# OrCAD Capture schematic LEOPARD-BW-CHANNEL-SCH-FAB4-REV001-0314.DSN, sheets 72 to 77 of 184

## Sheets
72 111_AST1250 HARDWARE TRAPPING: size Custom; title: AST1250 HARDWARE STRAPPING
73 110_AST1250 POWER: size A3; title: AST1250 POWER
74 107_AST1250 PCIE_LPC_DDR3_I2C: size Custom; title: AST1250 PCIE_LPC_DDR3_I2C
75 106_10000uF CAPACITORS: size Custom; title: 10000uF CAPACITORS
76 105_AST1250 HEARTBEAT_ADC: size A3; title: AST1250 HEARTBEAT_ADC
77 104_SMBUS HEADER: size A3; title: SMBUS HEADER

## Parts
sheet 104_SMBUS HEADER
JP8  FCI-CON2-S-GP  [680001-202HLF]
JP9  FCI-CON2-S-GP  [680001-202HLF]
JP10  FCI-CON2-S-GP  [680001-202HLF]
JP12  FCI-CON2-S-GP  [680001-202HLF]
sheet 105_AST1250 HEARTBEAT_ADC
C7265  SC1U10V2KX-4-GP  [C402H22]
C7266  SCD1U16V2KX-3GP  [C402H22]
C7267  SCD1U16V2KX-3GP  [C402H22]
C7269  SCD1U16V2KX-3GP  [C402H22]
C7270  SCD1U16V2KX-3GP  [C402H22]
C7271  SCD1U16V2KX-3GP  [C402H22]
C7281  SCD1U16V2KX-3GP  [C402H22]
C7283  SCD1U16V2KX-3GP  [C402H22]
C7285  SC1U10V2KX-4-GP  [C402H22]
LED63  LED-G-62-GP-U  [LED1608AKH36]
LED64  LED-G-62-GP-U  [LED1608AKH36]
R2082  5K6R2F-2-GP  [R402H16]
R2083  1K8R2F-GP  [R402H16]
R2084  330R2J-3-GP  [R402H16]
R2085  1KR2F-3-GP  [R402H16]
R2086  1KR2F-3-GP  [R402H16]
R2087  1KR2F-3-GP  [R402H16]
R2088  1KR2F-3-GP  [R402H16]
R2089  1K2R2F-1-GP  [R402H16]
R2090  130R2F-1-GP  [R402H16]
R2092  1KR2F-3-GP  [R402H16]
R2093  1K2R2F-1-GP  [R402H16]
R2094  130R2F-1-GP  [R402H16]
R2097  1KR2F-3-GP  [R402H16]
R2104  1KR2F-3-GP  [R402H16]
R2105  1K8R2F-GP  [R402H16]
R2116  330R2J-3-GP  [R402H16]
R2124  0R2J-2-GP  [R402H16]
R2125  0R2J-2-GP  [R402H16]
R2128  0R2J-2-GP  [R402H16]
R2130  1KR2F-3-GP  [R402H16]
U150  SN74LVC06APW-GP-U  [TSOIC14H48]  (sections A,B,C,D,E,F)
sheet 106_10000uF CAPACITORS
TC3  SE680U16VM-4-GP  [SE421740H414]
TC4  SE680U16VM-4-GP  [SE421740H414]
TC5  SE680U16VM-4-GP  [SE421740H414]
TC10  SE680U16VM-4-GP  [SE421740H414]
TC11  SE680U16VM-4-GP  [SE421740H414]
TC12  SE680U16VM-4-GP  [SE421740H414]
TC15  SE680U16VM-4-GP  [SE421740H414]
sheet 107_AST1250 PCIE_LPC_DDR3_I2C
BMC1  AST1250A1-GP  [BGA408D19H52]  (sections A,B,C,D)
C115  SCD1U16V2KX-3GP  [C402H22]
C118  SCD1U16V2KX-3GP  [C402H22]
C121  SC1U16V3KX-5GP  [C603H36]
C124  SCD1U16V2KX-3GP  [C402H22]
C127  SC10U6D3V5KX-4GP  [C805H58]
C130  SCD1U16V2KX-3GP  [C402H22]
C133  SCD1U16V2KX-3GP  [C402H22]
C136  SCD1U16V2KX-3GP  [C402H22]
C139  SCD1U16V2KX-3GP  [C402H22]
C142  SCD1U16V2KX-3GP  [C402H22]
C145  SCD1U16V2KX-3GP  [C402H22]
C148  SCD1U16V2KX-3GP  [C402H22]
C149  SCD01U25V2KX-3GP  [C402H22]
C150  SCD1U16V2KX-3GP  [C402H22]
C151  SCD1U16V2KX-3GP  [C402H22]
C152  SCD01U25V2KX-3GP  [C402H22]
C707  SCD1U16V2KX-3GP  [C402H22]
C718  SCD1U16V2KX-3GP  [C402H22]
Q28  LMBT3904LT1G-GP  [SOT23CBE2D4H44]
R231  10KR2F-2-GP  [R402H16]
R402  0R2J-2-GP  [R402H16]
R411  191R2F-GP  [R402H16]
R422  0R2J-2-GP  [R402H16]
R656  0R2J-2-GP  [R402H16]
R657  100KR2F-L1-GP  [R402H16]
R712  4K7R2F-GP  [R402H16]
R714  4K7R2F-GP  [R402H16]
R810  4K7R2F-GP  [R402H16]
R815  1KR2F-3-GP  [R402H16]
R817  1KR2F-3-GP  [R402H16]
R822  240R2F-1-GP  [R402H16]
R823  1KR2F-3-GP  [R402H16]
R943  4K7R2F-GP  [R402H16]
R2034  1KR2J-1-GP  [R402H16]
R2035  1KR2J-1-GP  [R402H16]
R2036  1KR2F-3-GP  [R402H16]
R2037  1KR2F-3-GP  [R402H16]
R2038  1KR2F-3-GP  [R402H16]
R2039  1KR2F-3-GP  [R402H16]
R2040  1KR2F-3-GP  [R402H16]
R2041  2K2R2F-GP  [R402H16]
R2042  2K2R2F-GP  [R402H16]
R2046  1KR2F-3-GP  [R402H16]
R2047  4K7R2F-GP  [R402H16]
R2048  2K2R2F-GP  [R402H16]
R2049  2K2R2F-GP  [R402H16]
R2050  4K7R2F-GP  [R402H16]
R2051  4K7R2F-GP  [R402H16]
R2052  4K7R2F-GP  [R402H16]
R2055  2K2R2F-GP  [R402H16]
R2091  100KR2F-L1-GP  [R402H16]
R2095  2K2R2F-GP  [R402H16]
R2096  4K7R2F-GP  [R402H16]
U21  NTJD4001NT1G-1-GP  [SOT-363H44]
U33  NT5CB64M16FP-DH-GP  [BGA96D0913H48]
sheet 110_AST1250 POWER
C156  SCD1U16V2KX-3GP  [C402H22]
C157  SC1U10V2KX-4-GP  [C402H22]
C158  SCD1U16V2KX-3GP  [C402H22]
C159  SC1U10V2KX-4-GP  [C402H22]
C161  SCD1U16V2KX-3GP  [C402H22]
C163  SC1U10V2KX-4-GP  [C402H22]
C165  SC220P50V2KX-3GP  [C402H22]
C166  SCD1U16V2KX-3GP  [C402H22]
C167  SC1U10V2KX-4-GP  [C402H22]
C169  SC1U10V2KX-4-GP  [C402H22]
C170  SCD1U16V2KX-3GP  [C402H22]
C171  SC1U10V2KX-4-GP  [C402H22]
C172  SC1U10V2KX-4-GP  [C402H22]
C175  SC1U10V2KX-4-GP  [C402H22]
C178  SC4D7U16V5KX-1-GP  [C805H56]
C184  SCD1U16V2KX-3GP  [C402H22]
C190  SC220P50V2KX-3GP  [C402H22]
C193  SC1U10V2KX-4-GP  [C402H22]
C196  SC1U10V2KX-4-GP  [C402H22]
C197  SC100P50V2JN-3GP  [C402H22]
C198  SC1U10V2KX-4-GP  [C402H22]
C199  SC100P50V2JN-3GP  [C402H22]
C200  SC1U10V2KX-4-GP  [C402H22]
C201  SC1U10V2KX-4-GP  [C402H22]
C202  SC1U10V2KX-4-GP  [C402H22]
C203  SC1U10V2KX-4-GP  [C402H22]
C300  SC100P50V2JN-3GP  [C402H22]
C301  SC1U10V2KX-4-GP  [C402H22]
C302  SC1U10V2KX-4-GP  [C402H22]
C304  SC1U10V2KX-4-GP  [C402H22]
C305  SC1U10V2KX-4-GP  [C402H22]
C306  SC1U10V2KX-4-GP  [C402H22]
C308  SC1U10V2KX-4-GP  [C402H22]
C314  SC100P50V2JN-3GP  [C402H22]
L8  MMZ2012S601ATA1N-GP  [L805H42]
L9  MMZ2012S601ATA1N-GP  [L805H42]
L10  MMZ2012S601ATA1N-GP  [L805H42]
L11  MMZ2012S601ATA1N-GP  [L805H42]
R939  2K74R3F-GP  [R603H22]
R940  49K9R2F-L-GP  [R402H16]
sheet 111_AST1250 HARDWARE TRAPPING
JP1  FCI-CON3-S1-GP  [68001-203HLF]
R538  3K3R2F-2-GP  [R402H16]
R547  3K3R2F-2-GP  [R402H16]
R601  3K3R2F-2-GP  [R402H16]
R606  3K3R2F-2-GP  [R402H16]
R1060  3K3R2F-2-GP  [R402H16]
R1061  3K3R2F-2-GP  [R402H16]
R1062  3K3R2F-2-GP  [R402H16]
R1063  3K3R2F-2-GP  [R402H16]
R1064  3K3R2F-2-GP  [R402H16]
R1065  3K3R2F-2-GP  [R402H16]
R1066  3K3R2F-2-GP  [R402H16]
R1067  3K3R2F-2-GP  [R402H16]
R1068  3K3R2F-2-GP  [R402H16]
R1069  3K3R2F-2-GP  [R402H16]
R1070  3K3R2F-2-GP  [R402H16]
R1071  3K3R2F-2-GP  [R402H16]
R1072  3K3R2F-2-GP  [R402H16]
R1073  3K3R2F-2-GP  [R402H16]
R1074  3K3R2F-2-GP  [R402H16]
R1075  3K3R2F-2-GP  [R402H16]
R1076  3K3R2F-2-GP  [R402H16]
R1077  3K3R2F-2-GP  [R402H16]
R1078  3K3R2F-2-GP  [R402H16]
R1079  3K3R2F-2-GP  [R402H16]
R1080  3K3R2F-2-GP  [R402H16]
R1081  3K3R2F-2-GP  [R402H16]
R1082  3K3R2F-2-GP  [R402H16]
R1083  3K3R2F-2-GP  [R402H16]
R1084  3K3R2F-2-GP  [R402H16]
R1085  3K3R2F-2-GP  [R402H16]
R1086  3K3R2F-2-GP  [R402H16]
R1087  3K3R2F-2-GP  [R402H16]

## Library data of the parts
JP8-JP10 JP12 = FCI-CON2-S-GP: HEAD ML 1R2P 68001-202HLF; Category: PCH; GREENDFACTOR: R_SA;; Package Type: CONN-G4; Part Number: 21.65007.102; Part Type: CONN-G4; SPEC: http://wpqssvr.wistron.com.tw:7001/wpqs/servlet/COM.qpart.Attachment?PartNumber=21.65007.102
C157 C159 C163 C167 C169 C171 C172 C175 C193 C196 C198 C200-C203 C301 C302 C304-C306 C308 C7265 C7285 = SC1U10V2KX-4-GP: CHIP CAP C 1U 10V K 0402 X6S; GREENDFACTOR: R2_SA;HF_SA;; Part Number: 78.10523.8FL; Part Type: SMD-BCG6; SPEC: http://wpqssvr.wistron.com.tw:7001/wpqs/servlet/COM.qpart.Attachment?PartNumber=78.10523.8FL
C7266 C7267 C7269-C7271 C7281 C7283 = SCD1U16V2KX-3GP: CHIP CAP C 0.1U 16V K0402 X7R; CATEGORIES: CAP_1.xV; GREENDFACTOR: R2_SA;HF_SA;G_SA;; MAIN_SOURCE: M; Part Number: 78.10421.2FL; Part Type: SMD-BCG; SPEC: http://wpqssvr.wistron.com.tw:7001/wpqs/servlet/COM.qpart.Attachment?PartNumber=78.10421.2FL
LED63 LED64 = LED-G-62-GP-U: LED GREEN LTST-C190GKT SMD; Alternate: 83.19213.I70; Category: BMC; DESCRIPTIO: LED GREEN LTST-C190GKT SMD; GREENDFACTOR: R2_SA;; Package Type: DISCRET-G9; Part Number: 83.00190.Q70; Part Type: DISCRET-G9; SPEC: http://wpqssvr.wistron.com.tw:7001/wpqs/servlet/COM.qpart.Attachment?PartNumber=83.00190.Q70; VENDORPARTNUMBER: LTST-C190GKT
R2082 = 5K6R2F-2-GP: CHIP RES 5.6K F 1/16W 0402(ROH; Category: HW monitor; DESCRIPTIO: CHIP RES 5.6K F 1/16W 0402(ROH; GREENDFACTOR: R2_SA;HF_SA;G_SA;; Package Type: SMD-RG; Part Number: 64.56015.6DL; Part Type: SMD-RG; SPEC: http://wpqssvr.wistron.com.tw:7001/wpqs/servlet/COM.qpart.Attachment?PartNumber=64.56015.6DL; VENDORPARTNUMBER: RM04FTN5601/RTT025601FTH/RR0510S-562-FN/RC0402FR-075K6L
R2083 R2105 = 1K8R2F-GP: CHIP RES 1.8K F 1/16W 0402; Category: HW monitor; DESCRIPTIO: CHIP RES 1.8K F 1/16W 0402; GREENDFACTOR: R2_SA;HF_SA;G_SA;; Package Type: SMD-RG; Part Number: 64.18015.6DL; Part Type: SMD-RG; SPEC: http://wpqssvr.wistron.com.tw:7001/wpqs/servlet/COM.qpart.Attachment?PartNumber=64.18015.6DL; VENDORPARTNUMBER: RM04FTN1801/RTT021801FTH/RR0510S-182-FN /RC0402FR-071K8L
R2084 R2116 = 330R2J-3-GP: CHIP RES 330 J 1/16W 0402; Category: BMC; DESCRIPTIO: CHIP RES 330 J 1/16W 0402; GREENDFACTOR: R2_SA;HF_SA;G_SA;; Package Type: SMD-RG; Part Number: 63.33134.1DL; Part Type: SMD-RG; SPEC: http://wpqssvr.wistron.com.tw:7001/wpqs/servlet/COM.qpart.Attachment?PartNumber=63.33134.1DL; VENDORPARTNUMBER: RM04JTN331 / RTT02331JTH / RR0510S-331-JN / RC0402JR-07330RL/WR04X331JTL
R2085-R2088 R2092 R2097 R2104 = 1KR2F-3-GP: CHIP RES 1K F 1/16W 0402; Category: HW monitor; DESCRIPTIO: CHIP RES 1K F 1/16W 0402; GREENDFACTOR: R2_SA;HF_SA;G_SA;; Package Type: SMD-RG; Part Number: 64.10015.6DL; Part Type: SMD-RG; SPEC: http://wpqssvr.wistron.com.tw:7001/wpqs/servlet/COM.qpart.Attachment?PartNumber=64.10015.6DL; VENDORPARTNUMBER: RM04FTN1001 / RTT021001FTH / RR0510S-1001-FN / RC0402FR-071KL/WR04X1001FTL
R2089 R2093 = 1K2R2F-1-GP: CHIP RES 1.2K F 1/16W 0402; Category: BMC; DESCRIPTIO: CHIP RES 1.2K F 1/16W 0402; GREENDFACTOR: R2_SA;HF_SA;G_SA;; Package Type: SMD-RG; Part Number: 64.12015.6DL; Part Type: SMD-RG; SPEC: http://wpqssvr.wistron.com.tw:7001/wpqs/servlet/COM.qpart.Attachment?PartNumber=64.12015.6DL; VENDORPARTNUMBER: RM04FTN1201/RTT021201FTH/RR0510S-1201-FN/RC0402FR-071K2L/WR04X1201FTL
R2090 R2094 = 130R2F-1-GP: CHIP RES 130 F 1/16W 0402; GREENDFACTOR: R2_SA;HF_SA;G_SA;; Part Number: 64.13005.6DL; Part Type: SMD-RG; SPEC: http://wpqssvr.wistron.com.tw:7001/wpqs/servlet/COM.qpart.Attachment?PartNumber=64.13005.6DL
R2124 R2128 = 0R2J-2-GP: CHIP RES 0 J 1/16W 0402; Category: LOM - i350; DESCRIPTIO: CHIP RES 0 J 1/16W 0402; GREENDFACTOR: R2_SA;HF_SA;G_SA;; Package Type: SMD-RG; Part Number: 63.R0034.1DL; Part Type: SMD-RG; SPEC: http://wpqssvr.wistron.com.tw:7001/wpqs/servlet/COM.qpart.Attachment?PartNumber=63.R0034.1DL; VENDORPARTNUMBER: RM04JTN0/RTT02000JTH/RR0510X-000-XN/RC0402JR-070RL/WR04X000 PTL
R2125 = 0R2J-2-GP: CHIP RES 0 J 1/16W 0402; Category: LOM - i350; DESCRIPTIO: CHIP RES 0 J 1/16W 0402; GREENDFACTOR: R2_SA;HF_SA;G_SA;; POP?: NOPOP; Package Type: SMD-RG; Part Number: 63.R0034.1DL; Part Type: SMD-RG; SPEC: http://wpqssvr.wistron.com.tw:7001/wpqs/servlet/COM.qpart.Attachment?PartNumber=63.R0034.1DL; VENDORPARTNUMBER: RM04JTN0/RTT02000JTH/RR0510X-000-XN/RC0402JR-070RL/WR04X000 PTL
R2130 = 1KR2F-3-GP: CHIP RES 1K F 1/16W 0402; Category: HW monitor; DESCRIPTIO: CHIP RES 1K F 1/16W 0402; GREENDFACTOR: R2_SA;HF_SA;G_SA;; POP?: NOPOP; Package Type: SMD-RG; Part Number: 64.10015.6DL; Part Type: SMD-RG; SPEC: http://wpqssvr.wistron.com.tw:7001/wpqs/servlet/COM.qpart.Attachment?PartNumber=64.10015.6DL; VENDORPARTNUMBER: RM04FTN1001 / RTT021001FTH / RR0510S-1001-FN / RC0402FR-071KL/WR04X1001FTL
U150 = SN74LVC06APW-GP-U: IC CMOS SN74LVC06APWR TSSOP14P; GREENDFACTOR: R2_SA;; Part Number: 73.07406.BHB; Part Type: TTL-G3; SPEC: http://wpqssvr.wistron.com.tw:7001/wpqs/servlet/COM.qpart.Attachment?PartNumber=73.07406.BHB
TC3-TC5 TC10-TC12 TC15 = SE680U16VM-4-GP: CHIP CAP EL 680U 16V M 10*10.5 TZV; GREENDFACTOR: R2_C;; Part Number: 079.6871D.0011; Part Type: SMD-TCG2; SPEC: http://wpqssvr.wistron.com.tw:7001/wpqs/servlet/COM.qpart.Attachment?PartNumber=079.6871D.0011
BMC1 = AST1250A1-GP: IC BMC AST1250A1-GP TFBGA 408P; GREENDFACTOR: R2_C;; Part Number: 71.01250.A0U; Part Type: ASIC2-G7; SPEC: http://wpqssvr.wistron.com.tw:7001/wpqs/servlet/COM.qpart.Attachment?PartNumber=71.01250.A0U
C115 C118 C124 C130 C136 C139 C142 C145 C148 C150 C151 = SCD1U16V2KX-3GP: CHIP CAP C 0.1U 16V K0402 X7R; CATEGORIES: CAP_1.xV; Category: BMC; DESCRIPTIO: CHIP CAP C 0.1U 16V K0402 X7R; GREENDFACTOR: R2_SA;HF_SA;G_SA;; Level: SMD; MAIN_SOURCE: M; Package Type: SMD-BCG; Part Number: 78.10421.2FL; Part Type: SMD-BCG; SPEC: http://wpqssvr.wistron.com.tw:7001/wpqs/servlet/COM.qpart.Attachment?PartNumber=78.10421.2FL; Status: POP
C121 = SC1U16V3KX-5GP: CHIP CAP C 1U 16V K0603 X7R; CATEGORIES: CAP_Small; Category: BMC; GREENDFACTOR: R2_SA;HF_SA;G_SA;; Level: SMD; MAIN_SOURCE: M; Part Number: 78.10521.2BL; Part Type: SMD-BCG3; SPEC: http://wpqssvr.wistron.com.tw:7001/wpqs/servlet/COM.qpart.Attachment?PartNumber=78.10521.2BL; Status: POP
C127 = SC10U6D3V5KX-4GP: CHIP CAP C 10U 6.3V K0805 X7R; GREENDFACTOR: R2_SA;HF_SA;G_SA;; Part Number: 78.10620.21L; Part Type: SMD-BCG; SPEC: http://wpqssvr.wistron.com.tw:7001/wpqs/servlet/COM.qpart.Attachment?PartNumber=78.10620.21L
C133 C158 C184 = SCD1U16V2KX-3GP: CHIP CAP C 0.1U 16V K0402 X7R; CATEGORIES: CAP_1.xV; Category: BMC; GREENDFACTOR: R2_SA;HF_SA;G_SA;; Level: SMD; MAIN_SOURCE: M; Part Number: 78.10421.2FL; Part Type: SMD-BCG; SPEC: http://wpqssvr.wistron.com.tw:7001/wpqs/servlet/COM.qpart.Attachment?PartNumber=78.10421.2FL; Status: POP
C149 C152 = SCD01U25V2KX-3GP: CHIP 0.01U 25V K0402 X7R(ROHS); Category: BMC; GREENDFACTOR: R2_SA;HF_SA;G_SA;; Level: SMD; Part Number: 78.10322.2FL; Part Type: SMD-BCG; SPEC: http://wpqssvr.wistron.com.tw:7001/wpqs/servlet/COM.qpart.Attachment?PartNumber=78.10322.2FL; Status: POP
C707 C718 = SCD1U16V2KX-3GP: CHIP CAP C 0.1U 16V K0402 X7R; Category: PCH; GREENDFACTOR: R_SA;HF_SA;G_SA;; POP?: NOPOP; Part Number: 78.10421.2FL; Quotation: 13_8; Type: SMD
Q28 = LMBT3904LT1G-GP: XTOR LMBT3904LT1G NPN SOT-23; GREENDFACTOR: R2_SA;HF_SA;G_SA;; POP?: NOPOP; Part Number: 84.T3904.H11; Part Type: DISCRET-G6; SPEC: http://wpqssvr.wistron.com.tw:7001/wpqs/servlet/COM.qpart.Attachment?PartNumber=84.T3904.H11
R231 = 10KR2F-2-GP: CHIP RES 10K F 1/16W 0402; GREENDFACTOR: R2_SA;HF_SA;G_SA;; Part Number: 64.10025.6DL; Part Type: SMD-RG; SPEC: http://wpqssvr.wistron.com.tw:7001/wpqs/servlet/COM.qpart.Attachment?PartNumber=64.10025.6DL
R402 = 0R2J-2-GP: CHIP RES 0 J 1/16W 0402; Category: PCH; DESCRIPTIO: CHIP RES 0 J 1/16W 0402; GREENDFACTOR: R2_SA;HF_SA;G_SA;; POP?: NOPOP; Package Type: SMD-RG; Part Number: 63.R0034.1DL; Part Type: SMD-RG; SPEC: http://wpqssvr.wistron.com.tw:7001/wpqs/servlet/COM.qpart.Attachment?PartNumber=63.R0034.1DL; VENDORPARTNUMBER: RM04JTN0/RTT02000JTH/RR0510X-000-XN/RC0402JR-070RL/WR04X000 PTL
R411 = 191R2F-GP: CHIP RES 191 F 1/16W 0402; GREENDFACTOR: R2_SA;HF_SA;G_SA;; Part Number: 64.19105.6DL; Part Type: SMD-RG1; SPEC: http://wpqssvr.wistron.com.tw:7001/wpqs/servlet/COM.qpart.Attachment?PartNumber=64.19105.6DL
R422 = 0R2J-2-GP: CHIP RES 0 J 1/16W 0402; Category: PCH; DESCRIPTIO: CHIP RES 0 J 1/16W 0402; GREENDFACTOR: R2_SA;HF_SA;G_SA;; Package Type: SMD-RG; Part Number: 63.R0034.1DL; Part Type: SMD-RG; SPEC: http://wpqssvr.wistron.com.tw:7001/wpqs/servlet/COM.qpart.Attachment?PartNumber=63.R0034.1DL; VENDORPARTNUMBER: RM04JTN0/RTT02000JTH/RR0510X-000-XN/RC0402JR-070RL/WR04X000 PTL
R656 = 0R2J-2-GP: CHIP RES 0 J 1/16W 0402; GREENDFACTOR: R2_SA;HF_SA;G_SA;; POP?: NOPOP; Package Type: SMD-RG; Part Number: 63.R0034.1DL; SPEC: http://wpqssvr.wistron.com.tw:7001/wpqs/servlet/COM.qpart.Attachment?PartNumber=63.R0034.1DL
R657 = 100KR2F-L1-GP: CHIP RES 100K F 1/16W 0402; Category: BMC; GREENDFACTOR: R2_SA;R_SA;HF_SA;G_SA;; Level: SMD; Part Number: 64.10035.6DL; Part Type: SMD-RG; SPEC: http://wpqssvr.wistron.com.tw:7001/wpqs/servlet/COM.qpart.Attachment?PartNumber=64.10035.6DL; Status: POP
R712 = 4K7R2F-GP: CHIP RES 4.7K F 1/16W 0402; GREENDFACTOR: R2_SA;HF_SA;G_SA;; Package Type: RCL_GP; Part Number: 64.47015.6DL; SPEC: http://wpqssvr.wistron.com.tw:7001/wpqs/servlet/COM.qpart.Attachment?PartNumber=64.47015.6DL
R714 = 4K7R2F-GP: CHIP RES 4.7K F 1/16W 0402; GREENDFACTOR: R2_SA;HF_SA;G_SA;; POP?: NOPOP; Package Type: RCL_GP; Part Number: 64.47015.6DL; SPEC: http://wpqssvr.wistron.com.tw:7001/wpqs/servlet/COM.qpart.Attachment?PartNumber=64.47015.6DL
R810 = 4K7R2F-GP: CHIP RES 4.7K F 1/16W 0402; Category: BMC; DESCRIPTIO: CHIP RES 4.7K F 1/16W 0402; GREENDFACTOR: R2_SA;HF_SA;G_SA;; Level: SMD; Package Type: RCL_GP; Part Number: 64.47015.6DL; Part Type: RCL_GP; SPEC: http://wpqssvr.wistron.com.tw:7001/wpqs/servlet/COM.qpart.Attachment?PartNumber=64.47015.6DL; Status: POP
R815 R823 = 1KR2F-3-GP: CHIP RES 1K F 1/16W 0402; Category: BMC; GREENDFACTOR: R2_SA;R_SA;HF_SA;G_SA;; Level: SMD; Part Number: 64.10015.6DL; Part Type: SMD-RG; SPEC: http://wpqssvr.wistron.com.tw:7001/wpqs/servlet/COM.qpart.Attachment?PartNumber=64.10015.6DL; Status: POP
R817 = 1KR2F-3-GP: CHIP RES 1K F 1/16W 0402; Category: BMC; DESCRIPTIO: CHIP RES 1K F 1/16W 0402; GREENDFACTOR: R2_SA;R_SA;HF_SA;G_SA;; Level: SMD; Package Type: SMD-RG; Part Number: 64.10015.6DL; Part Type: SMD-RG; SPEC: http://wpqssvr.wistron.com.tw:7001/wpqs/servlet/COM.qpart.Attachment?PartNumber=64.10015.6DL; Status: POP
R822 = 240R2F-1-GP: CHIP RES 240 F 1/16W 0402(ROHS; Category: BMC; DESCRIPTIO: CHIP RES 240 F 1/16W 0402(ROHS; GREENDFACTOR: R2_SA;HF_SA;G_SA;; Level: SMD; Package Type: SMD-RG; Part Number: 64.24005.6DL; Part Type: SMD-RG; SPEC: http://wpqssvr.wistron.com.tw:7001/wpqs/servlet/COM.qpart.Attachment?PartNumber=64.24005.6DL; Status: POP
R943 = 4K7R2F-GP: CHIP RES 4.7K F 1/16W 0402; Category: CPU SIDE BAND; POP?: NOPOP; Part Number: 64.47015.6DL; Part Type: RCL_GP
R2034 R2035 = 1KR2J-1-GP: CHIP RES 1K J 1/16W 0402; GREENDFACTOR: R2_SA;HF_SA;G_SA;; Part Number: 63.10234.1DL; Part Type: SMD-RG; SPEC: http://wpqssvr.wistron.com.tw:7001/wpqs/servlet/COM.qpart.Attachment?PartNumber=63.10234.1DL
R2036-R2040 R2046 = 1KR2F-3-GP: CHIP RES 1K F 1/16W 0402; GREENDFACTOR: R2_SA;HF_SA;G_SA;; Package Type: SMD-RG; Part Number: 64.10015.6DL; SPEC: http://wpqssvr.wistron.com.tw:7001/wpqs/servlet/COM.qpart.Attachment?PartNumber=64.10015.6DL
R2041 R2042 R2048 R2049 R2055 R2095 = 2K2R2J-2-GP: CHIP RES 2.2K F 1/16W 0402; Category: BMC; DESCRIPTIO: CHIP RES 2.2K J 1/16W 0402; GREENDFACTOR: R2_SA;HF_SA;G_SA;; Package Type: RCL_GP; Part Number: 64.22015.6DL; Part Type: RCL_GP; SPEC: http://wpqssvr.wistron.com.tw:7001/wpqs/servlet/COM.qpart.Attachment?PartNumber=64.22015.6DL; VENDORPARTNUMBER: RM04FTN2201/RTT022201FTH/RR0510S-222-FN/RC0402FR-072K2L
R2047 R2050 R2096 = 4K7R2F-GP: CHIP RES 4.7K F 1/16W 0402; Category: BMC; DESCRIPTIO: CHIP RES 4.7K F 1/16W 0402; GREENDFACTOR: R2_SA;HF_SA;G_SA;; Package Type: RCL_GP; Part Number: 64.47015.6DL; Part Type: RCL_GP; SPEC: http://wpqssvr.wistron.com.tw:7001/wpqs/servlet/COM.qpart.Attachment?PartNumber=64.47015.6DL; VENDORPARTNUMBER: RM04FTN4701/RTT024701FTH/RR0510S-472-FN/RC0402FR-074K7L/WR04X4701FTL
R2051 R2052 = 4K7R2F-GP: CHIP RES 4.7K F 1/16W 0402; Category: BMC; DESCRIPTIO: CHIP RES 4.7K F 1/16W 0402; GREENDFACTOR: R2_SA;HF_SA;G_SA;; POP?: NOPOP; Package Type: RCL_GP; Part Number: 64.47015.6DL; Part Type: RCL_GP; SPEC: http://wpqssvr.wistron.com.tw:7001/wpqs/servlet/COM.qpart.Attachment?PartNumber=64.47015.6DL; VENDORPARTNUMBER: RM04FTN4701/RTT024701FTH/RR0510S-472-FN/RC0402FR-074K7L/WR04X4701FTL
R2091 = 100KR2F-L1-GP: CHIP RES 100K F 1/16W 0402; Category: BMC; DESCRIPTIO: CHIP RES 100K F 1/16W 0402; GREENDFACTOR: R2_SA;HF_SA;G_SA;; Package Type: SMD-RG; Part Number: 64.10035.6DL; Part Type: SMD-RG; SPEC: http://wpqssvr.wistron.com.tw:7001/wpqs/servlet/COM.qpart.Attachment?PartNumber=64.10035.6DL; VENDORPARTNUMBER: RM04FTN1003 / RTT021003FTH / RR0510S-1003-FN / RC0402FR-07100KL/WR04X1003FTL
U21 = NTJD4001NT1G-1-GP: IC MOSFET NTJD4001NT1G NC SOT-363 6P; GREENDFACTOR: R2_SA;; Part Number: 75.04001.07C; Part Type: DISCRET-G5; SPEC: http://wpqssvr.wistron.com.tw:7001/wpqs/servlet/COM.qpart.Attachment?PartNumber=75.04001.07C
U33 = NT5CB64M16FP-DH-GP: IC SDRAM NT5CB64M16FP-DH FBGA 96BALLS; GREENDFACTOR: R2_SA;HF_SA;G_SA;; POP?: 72.41164.V0U; Part Number: 72.56416.P0U; Part Type: MEMORY-G4; SPEC: http://wpqssvr.wistron.com.tw:7001/wpqs/servlet/COM.qpart.Attachment?PartNumber=72.56416.P0U
C156 C166 C170 = SCD1U16V2KX-3GP: CHIP CAP C 0.1U 16V K0402 X7R; CATEGORIES: CAP_1.xV; Category: BMC; GREENDFACTOR: R2_SA;HF_SA;G_SA;; Level: SMD; MAIN_SOURCE: M; POP?: NOPOP; Part Number: 78.10421.2FL; Part Type: SMD-BCG; SPEC: http://wpqssvr.wistron.com.tw:7001/wpqs/servlet/COM.qpart.Attachment?PartNumber=78.10421.2FL; Status: POP
C161 = SCD47U6D3V2KX-GP: CHIP CAP C 0.1U 16V K0402 X7R; CATEGORIES: CAP_1.xV; Category: BMC; GREENDFACTOR: R2_SA;HF_SA;G_SA;; Level: SMD; MAIN_SOURCE: M; Part Number: 78.10421.2FL; Part Type: SMD-BCG; SPEC: http://wpqssvr.wistron.com.tw:7001/wpqs/servlet/COM.qpart.Attachment?PartNumber=78.10421.2FL; Status: POP
C165 C190 = SC220P50V2KX-3GP: CHIP CAP 220P50V K0402 X7R(ROH; CATEGORIES: CAP_Small; Category: BMC; GREENDFACTOR: R2_SA;HF_SA;G_SA;; Level: SMD; MAIN_SOURCE: M; Part Number: 78.22124.2FL; Part Type: SMD-BCG; SPEC: http://wpqssvr.wistron.com.tw:7001/wpqs/servlet/COM.qpart.Attachment?PartNumber=78.22124.2FL; Status: POP
C178 = SC4D7U16V5KX-1-GP: CHIP CAP C 4.7U 16V K0805 X7R; GREENDFACTOR: R2_SA;HF_SA;G_SA;; Part Number: 78.47521.21L; Part Type: SMD-BCG2; SPEC: http://wpqssvr.wistron.com.tw:7001/wpqs/servlet/COM.qpart.Attachment?PartNumber=78.47521.21L
C197 C199 = SC100P50V2JN-3GP: CHIP CAP 100P50V J0402 NPO(ROH; CATEGORIES: CAP_Small; Category: BMC; GREENDFACTOR: R2_SA;HF_SA;G_SA;; Level: SMD; MAIN_SOURCE: M; Part Number: 78.10134.1FL; Part Type: SMD-BCG; SPEC: http://wpqssvr.wistron.com.tw:7001/wpqs/servlet/COM.qpart.Attachment?PartNumber=78.10134.1FL; Status: POP
C300 C314 = SC220P50V2KX-3GP: CHIP CAP 100P50V J0402 NPO(ROH; CATEGORIES: CAP_Small; Category: BMC; GREENDFACTOR: R2_SA;HF_SA;G_SA;; Level: SMD; MAIN_SOURCE: M; Part Number: 78.10134.1FL; Part Type: SMD-BCG; SPEC: http://wpqssvr.wistron.com.tw:7001/wpqs/servlet/COM.qpart.Attachment?PartNumber=78.10134.1FL; Status: POP
L8-L11 = MMZ2012S601ATA1N-GP: CHIP BEAD MMZ2012S601ATA1N TDK; Category: BMC; GREENDFACTOR: R_C;; Level: SMD; Part Number: 68.00109.171; Part Type: DISCRET-G5; SPEC: http://wpqssvr.wistron.com.tw:7001/wpqs/servlet/COM.qpart.Attachment?PartNumber=68.00109.171; Status: POP
R939 = 2K74R3F-GP: CHIP RES 2.74K F 1/10W 0603; Category: BMC; Level: SMD; Part Number: 64.27415.55L; Part Type: RCL_GP; Status: POP
R940 = 49K9R2F-L-GP: CHIP RES 49.9K F 1/16W 0402; Category: BMC; GREENDFACTOR: R2_SA;R_SA;HF_SA;G_SA;; Level: SMD; POP?: POP; Part Number: 64.49925.6DL; Part Type: SMD-RG; SPEC: http://wpqssvr.wistron.com.tw:7001/wpqs/servlet/COM.qpart.Attachment?PartNumber=64.49925.6DL; Status: POP
JP1 = FCI-CON3-S1-GP: HEAD ML 1R3P ST 68001-203HLF; Category: PCH; GREENDFACTOR: R_SA;; Green Factor: R_SA;; Part Number: 21.61084.103; Part Type: CONN-G4; ROOM: IMMv2; S/D: DIP; SPEC: http://wpqssvr.wistron.com.tw:7001/wpqs/servlet/COM.qpart.Attachment?PartNumber=21.61084.103; Vender: FCI
R538 R1060 R1062 R1064 R1070 R1082 R1083 = 3K3R2F-2-GP: CHIP RES 3.3K F 1/16W 0402; Category: BMC; GREENDFACTOR: R2_SA;HF_SA;G_SA;; Level: SMD; Part Number: 64.33015.6DL; Part Type: SMD-RG; SPEC: http://wpqssvr.wistron.com.tw:7001/wpqs/servlet/COM.qpart.Attachment?PartNumber=64.33015.6DL
R547 R601 R606 R1061 R1063 R1065-R1069 R1071-R1081 R1084-R1086 = 3K3R2F-2-GP: CHIP RES 3.3K F 1/16W 0402; Category: BMC; GREENDFACTOR: R2_SA;HF_SA;G_SA;; Level: SMD; POP?: NOPOP; Part Number: 64.33015.6DL; Part Type: SMD-RG; SPEC: http://wpqssvr.wistron.com.tw:7001/wpqs/servlet/COM.qpart.Attachment?PartNumber=64.33015.6DL
R1087 = 3K3R2F-2-GP: CHIP RES 3.3K F 1/16W 0402; Category: BMC; GREENDFACTOR: R2_SA;HF_SA;G_SA;; Level: SMD; Part Number: 64.33015.6DL; Part Type: SMD-RG; SPEC: http://wpqssvr.wistron.com.tw:7001/wpqs/servlet/COM.qpart.Attachment?PartNumber=64.33015.6DL; Status: POP

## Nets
GND: BMC1.AA18(PLLVSS) BMC1.AA19(PLLVSS) BMC1.D21(PEAGND) BMC1.D22(PEAGND) BMC1.J9(GND) BMC1.J10(GND) BMC1.J11(GND) BMC1.J12(GND) BMC1.J13(GND) BMC1.J14(GND) BMC1.K9(GND) BMC1.K10(GND) BMC1.K11(GND) BMC1.K12(GND) BMC1.K13(GND) BMC1.K14(GND) BMC1.L9(GND) BMC1.L10(GND) BMC1.L11(GND) BMC1.L12(GND) BMC1.L13(GND) BMC1.L14(GND) BMC1.M9(GND) BMC1.M10(GND) BMC1.M11(GND) BMC1.M12(GND) BMC1.M13(GND) BMC1.M14(GND) BMC1.N9(GND) BMC1.N10(GND) BMC1.N11(GND) BMC1.N12(GND) BMC1.N13(GND) BMC1.N14(GND) BMC1.P4(ADCAVSS) BMC1.P9(GND) BMC1.P10(GND) BMC1.P11(GND) BMC1.P12(GND) BMC1.P13(GND) BMC1.P14(GND) BMC1.R5(DACAVSS) BMC1.V18(PLLVSS) C115.2 C118.2 C121.2 C124.2 C127.2 C130.2 C133.1 C136.2 C139.2 C142.2 C145.2 C148.2 C149.2 C150.2 C151.2 C157.2 C158.2 C159.2 C161.2 C163.2 C165.2 C166.1 C167.2 C169.2 C171.2 C172.2 C175.2 C178.2 C184.2 C190.2 C193.2 C196.2 C197.2 C198.2 C199.2 C200.2 C201.2 C202.2 C203.2 C300.2 C301.2 C302.2 C304.2 C305.2 C306.2 C308.2 C314.2 C7265.2 C7266.2 C7267.2 C7269.2 C7270.2 C7271.2 C7281.2 C7283.2 C7285.2 R411.2 R657.1 R815.2 R822.1 R939.1 R940.1 R2085.2 R2086.2 R2087.2 R2091.2 R2092.2 R2104.2 R2125.2 R2130.2 TC3.2 TC4.2 TC5.2 TC10.2 TC11.2 TC12.2 TC15.2 U21.1(S1) U21.4(S2) U33.A9(VSS) U33.B1(VSSQ) U33.B3(VSS) U33.B9(VSSQ) U33.D1(VSSQ) U33.D8(VSSQ) U33.E1(VSS) U33.E2(VSSQ) U33.E8(VSSQ) U33.F9(VSSQ) U33.G1(VSSQ) U33.G8(VSS) U33.G9(VSSQ) U33.J2(VSS) U33.J8(VSS) U33.M1(VSS) U33.M9(VSS) U33.P1(VSS) U33.P9(VSS) U33.T1(VSS) U33.T9(VSS) U150.5(I) U150.7(GND) U150.9(I) U150.13(I) ; also on sheet 1 2 3 4 5 6 7 8 9 10 11 12 13 14 15 16 17 18 19 20 21 22 23 24 25 26 27 28 29 30 31 32 33 34 35 36 37 38 39 44 46 47 49 50 51 52 53 54 55 56 57 58 59 60 61 62 63 64 65 66 69 70 71 78 79 80 81 82 83 84 86 87 88 89 90 91 92 93 94 95 96 97 98 99 100 101 102 103 104 105 106 107 108 109 110 111 112 113 114 115 116 117 118 119 128 129 138 139 159 160 161 166 168 169 170 171 172 173 174 175 176 177 180 181 182 183 184
P1V05_STBY_PCH: R2124.1 ; also on sheet 9 45 87
P1V8_STBY: R2128.1 ; also on sheet 5 6 7 8
P1V26_STBY: BMC1.F14(IV12D) BMC1.F15(IV12D) BMC1.K6(IV12D) BMC1.K17(PEAV12) BMC1.L6(IV12D) BMC1.L17(IV12D) BMC1.P6(IV12D) BMC1.P17(IV12D) BMC1.R6(IV12D) BMC1.R17(IV12D) BMC1.U12(IV12D) BMC1.U13(IV12D) BMC1.Y18(MPLLDV12) C157.1 C169.1 C172.1 C201.1 C203.1 C302.1 L9.1(F) ; also on sheet 5
P1V538_STBY: BMC1.U10(MVDD) BMC1.U11(MVDD) BMC1.U14(MVDD) BMC1.U15(MVDD) C115.1 C118.1 C124.1 C127.1 C130.1 C136.1 C142.1 C145.1 C148.1 C150.1 C151.1 C152.1 C163.1 C167.1 C193.1 C196.1 R817.2 R823.1 U33.A1(VDDQ) U33.A8(VDDQ) U33.B2(VDD) U33.C1(VDDQ) U33.C9(VDDQ) U33.D2(VDDQ) U33.D9(VDD) U33.E9(VDDQ) U33.F1(VDDQ) U33.G7(VDD) U33.H2(VDDQ) U33.H9(VDDQ) U33.K2(VDD) U33.K8(VDD) U33.N1(VDD) U33.N9(VDD) U33.R1(VDD) U33.R9(VDD) ; also on sheet 6
P3V3: R712.2 R943.1 R2088.1 ; also on sheet 1 3 8 45 46 48 49 52 54 58 65 78 83 84 87 90 91 94 95 96 100 101 102 161 166 168 173 174 177 180 181 182 183
P3V3_STBY: BMC1.F8(R2VDD) BMC1.F9(R2VDD) BMC1.F10(R1VDD) BMC1.F11(R1VDD) BMC1.F12(PV33D) BMC1.F13(PV33D) BMC1.H6(PV33D) BMC1.H17(PV33D) BMC1.J6(PV33D) BMC1.J17(PEAV33) BMC1.M6(PV33D) BMC1.M17(PV33D) BMC1.N6(PV33D) BMC1.N17(PV33D) BMC1.U8(PV33D) BMC1.U9(PV33D) C159.1 C165.1 C171.1 C175.1 C190.1 C200.1 C202.1 C301.1 C304.1 C305.1 C7265.1 C7285.1 L8.1(F) L10.1(F) L11.1(F) R231.2 R538.1 R547.1 R601.1 R606.1 R714.2 R810.2 R1060.1 R1061.1 R1062.1 R1063.1 R1064.1 R1065.1 R1066.1 R1067.1 R1068.1 R1069.1 R1070.1 R1071.1 R1072.1 R1073.1 R1074.1 R1075.1 R1076.1 R1077.1 R1078.1 R1079.1 R1080.1 R1081.1 R1082.1 R1083.1 R1084.1 R1085.1 R1086.1 R1087.2 R2034.2 R2035.2 R2036.2 R2037.2 R2038.2 R2039.2 R2040.2 R2041.2 R2042.2 R2046.2 R2047.2 R2048.2 R2049.2 R2050.2 R2051.2 R2052.2 R2055.2 R2084.1 R2089.1 R2093.1 R2095.2 R2096.2 R2097.1 R2116.1 U150.14(VCC) ; also on sheet 2 3 5 6 8 9 10 11 12 15 16 17 20 21 22 25 26 27 30 31 33 34 35 37 38 39 45 47 49 50 51 52 54 55 59 60 61 62 63 64 65 66 69 70 71 79 83 84 87 88 89 90 91 92 93 94 95 96 97 98 99 159 161 166 168 173 174 176 177 179 180 182 183 184
P5V: R2083.1 ; also on sheet 45 59 66 69 80 82 176
P5V_STBY: R2105.1 ; also on sheet 4 5 6 8 14 15 19 20 24 25 29 30 33 34 37 38 59 61 65 69 95
P12V_PCIE_HDD: R2082.1 ; also on sheet 59 80 82 94
P12V_STBY: TC3.1 TC4.1 TC5.1 TC10.1 TC11.1 TC12.1 TC15.1 ; also on sheet 2 3 4 7 9 10 11 12 13 17 18 22 23 27 28 32 36 59 60 95 104 105 106 107 108 109 110 111 112 113 114 115 116 117 118 119
V1PLLAV12: BMC1.W19(V1PLLAV12) BMC1.Y20(V2PLLAV12) C158.1 C197.1 C306.1 L9.2(S)
VBAT_MEAS_EN: BMC1.B16(GPIOD5_SD2DAT3) ; also on sheet 184
ADC_12V_PCIE: C7266.1 R2082.2 R2085.1 ; also on sheet 177
ADC_P1V05_STBY_PCH: C7283.1 R2124.2 R2125.1 ; also on sheet 177
ADC_P1V8_STBY: C7281.1 R2128.2 R2130.1 ; also on sheet 177
ADC_P3V3: C7270.1 R2088.2 R2092.1 ; also on sheet 177
ADC_P3V3_STBY: C7271.1 R2097.2 R2104.1 ; also on sheet 177
ADC_P5V: C7267.1 R2083.2 R2086.1 ; also on sheet 177
ADC_P5V_STBY: C7269.1 R2087.1 R2105.2 ; also on sheet 177
ADCAV33: BMC1.P3(ADCAV33) C156.1 C308.1 C314.1 L8.2(S)
ADCVREFFN: BMC1.K2(ADCVREFN) C166.2 C170.1
ADCVREFFP: BMC1.K1(ADCVREFP) C156.2 C170.2
ADCVREXT: BMC1.P2(ADCREXT) R940.2
AS_ROMA0_R: JP1.2 R1087.1
BMC_DDR3_GATE: R810.1 U21.2(G1) U21.3(D2)
BMC_DDR3_RST_N: R817.1 U21.6(D1) U33.T2(RESET#)
BMC_JTAG_SELECT: BMC1.H3(GPIOQ5_SDA14) ; also on sheet 50
BMC_LED_ACTIVE: U150.11(I) ; also on sheet 180
BMC_LED_CATERR: U150.1(I) ; also on sheet 180
BMC_LED_N: LED63.K U150.10(O)
BMC_LED_R_N: LED63.A R2084.2
BMC_PCIE_PERST_N: BMC1.K19(PERST#) R656.2 R657.2
BMC_PCIE_WAKE_N: BMC1.J22(PEWAKE#) R231.1 R402.2
BMC_PEREXT: BMC1.D20(PEREXT) R411.1
BMC_RESET_N: U21.5(G2) ; also on sheet 51 177
CATERR_LED_N: LED64.K U150.2(O) U150.4(O)
CATERR_LED_R_N: LED64.A R2116.2
CLK_33M_BMC1_LPC: BMC1.B20(LCLK) R2091.1 ; also on sheet 88
CLK_100M_PCH_BMC_DN: BMC1.G21(PEREFCLKN) ; also on sheet 92
CLK_100M_PCH_BMC_DP: BMC1.G22(PEREFCLKP) ; also on sheet 92
CPLD_LED_CATERR: U150.3(I) ; also on sheet 52
CPU0_THERMTRIP_N_BMC: BMC1.C4(GPIOC0_SD1CLK_SCL10) R2090.2
CPU1_THERMTRIP_N_BMC: BMC1.B3(GPIOC1_SD1CMD_SDA10) R2094.2
DACAV33: BMC1.P1(DACAV33) BMC1.T3(DACDV33) C161.1 C178.1 C300.1 L11.2(S)
DACRSET: BMC1.R1(DACRSET) R939.2
DDR_VREF: BMC1.V13(MVREF) C121.1 C133.2 C139.1 C149.1 C152.2 R815.1 R823.2 U33.H1(VREFDQ) U33.M8(VREFCA)
FM_BIOS_POST_CMPLT_N: BMC1.A16(GPIOD6_SD2CD#) ; also on sheet 90
FM_BMC_PCH_SCI_LPC_N: BMC1.C16(GPIOD4_SD2DAT2) ; also on sheet 90
FM_BMC_READY_N: BMC1.A2(GPIOC2_SD1DAT0_SCL11) ; also on sheet 51 52 166
FM_BMC_SMI_ACTIVE_N: BMC1.C3(GPIOC5_SD1DAT3_SDA12) Q28.C R422.1 R714.1
FM_CPU0_FIVR_FAULT_LVT3_N: BMC1.A18(GPIOD0_SD2CLK) ; also on sheet 96
FM_CPU0_THERMTRIP_LVC3_N: R2089.2 R2090.1 ; also on sheet 96 99
FM_CPU1_FIVR_FAULT_LVT3_N: BMC1.D16(GPIOD1_SD2CMD) ; also on sheet 96
FM_CPU1_THERMTRIP_LVC3_N: R2093.2 R2094.1 ; also on sheet 96 99
FM_CPU_CATERR_LVT3_N: BMC1.B17(GPIOD2_SD2DAT0) ; also on sheet 52 101
FM_MEM_THERM_EVENT_LVT3_N: BMC1.H2(GPIOQ6) ; also on sheet 98
FM_SLPS3_N: BMC1.B2(GPIOC6_SD1CD#_SCL13) ; also on sheet 51 52 59 90
FM_SLPS4_N: BMC1.A1(GPIOC7_SD1WP#_SDA13) ; also on sheet 51 90
FM_SMI_ACTIVE_N: Q28.E R422.2 R712.1 ; also on sheet 90
FM_THROTTLE_N_BMC: BMC1.A17(GPIOD3_SD2DAT1) ; also on sheet 183
IRQ_BMC_PCH_NMI_STBY: BMC1.D4(GPIOC4_SD1DAT2_SCL12) ; also on sheet 182
IRQ_IBMC_PCH_SMI: Q28.B R943.2
IRQ_LVC3_WAKE_N: R402.1 ; also on sheet 64 81 83 88 94 95 168
IRQ_SERIAL: BMC1.E17(LSIRQ) ; also on sheet 52 78 91
IRQ_SML0_ALERT_N: BMC1.H18(GPIOB2_SALT3) R2047.1 ; also on sheet 90
IRQ_SML1_PMBUS_ALERT_N: BMC1.J20(GPIOB1_SALT2) R2096.1 ; also on sheet 52 54 60 90
LAN_SMB_ALERT_N: BMC1.J21(GPIOB0_SALT1) R2050.1 ; also on sheet 64 94 95
LAN_SMB_CLK: BMC1.K21(SCL1) JP8.1 R2038.1 ; also on sheet 64 94 95
LAN_SMB_DAT: BMC1.K22(SDA1) JP8.2 R2039.1 ; also on sheet 64 94 95
LED_PWRBLINK_BMC: BMC1.H4(GPIOQ4_SCL14) ; also on sheet 65
LPC_FRAME_N: BMC1.A21(LFRAME#) ; also on sheet 52 78 90
LPC_LAD0: BMC1.B21(LAD0) ; also on sheet 78 90
LPC_LAD1: BMC1.A22(LAD1) ; also on sheet 78 90
LPC_LAD2: BMC1.F19(LAD2) ; also on sheet 78 90
LPC_LAD3: BMC1.C19(LAD3) ; also on sheet 78 90
MemA_0: BMC1.AB14(MA0) U33.N3(A0)
MemA_1: BMC1.W15(MA1) U33.P7(A1)
MemA_2: BMC1.V15(MA2) U33.P3(A2)
MemA_3: BMC1.Y16(MA3) U33.N2(A3)
MemA_4: BMC1.AB15(MA4) U33.P8(A4)
MemA_5: BMC1.W16(MA5) U33.P2(A5)
MemA_6: BMC1.AA15(MA6) U33.R8(A6)
MemA_7: BMC1.AB18(MA7) U33.R2(A7)
MemA_8: BMC1.AB16(MA8) U33.T8(A8)
MemA_9: BMC1.AA17(MA9) U33.R3(A9)
MemA_10: BMC1.Y15(MA10) U33.L7(A10/AP)
MemA_11: BMC1.AA16(MA11) U33.R7(A11)
MemA_12: BMC1.W17(MA12) U33.N7(A12/BC#)
MemA_13: BMC1.Y17(MA13) U33.T3(NC#T3)
MemA_14: BMC1.AB17(MA14) U33.T7(NC#T7)
MemBA_0: BMC1.W14(MBA0) U33.M2(BA0)
MemBA_1: BMC1.AA14(MBA1) U33.N8(BA1)
MemBA_2: BMC1.Y14(MBA2) U33.M3(BA2)
MemCASN: BMC1.AB13(MCAS#) U33.K3(CAS#)
MemCK_N: BMC1.AA12(MCK#) U33.K7(CK#)
MemCK_P: BMC1.AB12(MCK) U33.J7(CK)
MemCKE: BMC1.Y12(MCKE) U33.K9(CKE)
MemCSN: BMC1.AA13(MCS#) U33.L2(CS#)
MemDM_0: BMC1.W10(MDM0) U33.E7(DML)
MemDM_1: BMC1.V8(MDM1) U33.D3(DMU)
MemDQ_0: BMC1.W12(MDQ0) U33.H7(DQL7)
MemDQ_1: BMC1.V12(MDQ1) U33.H3(DQL4)
MemDQ_2: BMC1.AB11(MDQ2) U33.F8(DQL3)
MemDQ_3: BMC1.AA11(MDQ3) U33.F7(DQL1)
MemDQ_4: BMC1.Y11(MDQ4) U33.F2(DQL2)
MemDQ_5: BMC1.W11(MDQ5) U33.G2(DQL6)
MemDQ_6: BMC1.V11(MDQ6) U33.H8(DQL5)
MemDQ_7: BMC1.Y10(MDQ7) U33.E3(DQL0)
MemDQ_8: BMC1.V10(MDQ8) U33.D7(DQU0)
MemDQ_9: BMC1.AB9(MDQ9) U33.B8(DQU6)
MemDQ_10: BMC1.AA9(MDQ10) U33.A7(DQU4)
MemDQ_11: BMC1.Y9(MDQ11) U33.C3(DQU1)
MemDQ_12: BMC1.W9(MDQ12) U33.C2(DQU3)
MemDQ_13: BMC1.V9(MDQ13) U33.C8(DQU2)
MemDQ_14: BMC1.Y8(MDQ14) U33.A3(DQU7)
MemDQ_15: BMC1.W8(MDQ15) U33.A2(DQU5)
MemDQS_N0: BMC1.AA10(MDQS0#) U33.G3(DQSL#)
MemDQS_N1: BMC1.AB8(MDQS1#) U33.B7(DQSU#)
MemDQS_P0: BMC1.AB10(MDQS0) U33.F3(DQSL)
MemDQS_P1: BMC1.AA8(MDQS1) U33.C7(DQSU)
MemODT: BMC1.V14(MODT) U33.K1(ODT)
MemRASN: BMC1.W13(MRAS#) U33.J3(RAS#)
MemWEN: BMC1.Y13(MWE#) U33.L3(WE#)
MPLLAV33: BMC1.AB19(MPLLAV33) BMC1.V17(HPLLAV33) C184.1 C198.1 C199.1 L10.2(S)
P2E_WBG_BMC_RX_C_DN8: C707.2 ; also on sheet 92
P2E_WBG_BMC_RX_C_DP8: C718.2 ; also on sheet 92
P2E_WBG_BMC_RX_DN8: BMC1.E21(PETXN) C707.1
P2E_WBG_BMC_RX_DP8: BMC1.E22(PETXP) C718.1
P2E_WBG_BMC_TX_C_DN_8: BMC1.F22(PERXN) ; also on sheet 92
P2E_WBG_BMC_TX_C_DP_8: BMC1.F21(PERXP) ; also on sheet 92
PD_ZQ: R822.2 U33.L8(ZQ)
PWRGD_PCH_PWROK_BMC: BMC1.E15(GPIOD7_SD2WP#) ; also on sheet 52
PWRGD_SYS_PWROK_BMC: BMC1.H1(GPIOQ7) ; also on sheet 52
ROMA0: JP1.1 ; also on sheet 48 180
ROMA1: R1070.2 ; also on sheet 180
ROMA2: R547.2 ; also on sheet 180
ROMA3: R1074.2 ; also on sheet 180
ROMA4: R1077.2 ; also on sheet 180
ROMA5: R1063.2 ; also on sheet 180
ROMA6: R601.2 ; also on sheet 180
ROMA7: R1075.2 ; also on sheet 180
ROMA8: R1061.2 ; also on sheet 180
ROMA9: R606.2 ; also on sheet 180
ROMA10: R1064.2 ; also on sheet 180
ROMA11: R1084.2 ; also on sheet 180
ROMA12: R1082.2 ; also on sheet 180
ROMA13: R1080.2 ; also on sheet 180
ROMA14: R538.2 ; also on sheet 180
ROMA15: R1081.2 ; also on sheet 180
ROMA16: R1086.2 ; also on sheet 180
ROMA17: R1071.2 ; also on sheet 180
ROMA18: R1083.2 ; also on sheet 180
ROMA19: R1060.2 ; also on sheet 180
ROMA20: R1076.2 ; also on sheet 180
ROMA21: R1078.2 ; also on sheet 180
ROMA22: R1066.2 ; also on sheet 180
ROMA23: R1069.2 ; also on sheet 180
ROMD0_R: R1079.2 ; also on sheet 180
ROMD1_R: R1062.2 ; also on sheet 180
ROMD2: R1065.2 ; also on sheet 180
ROMD3: R1072.2 ; also on sheet 180
ROMD4: R1073.2 ; also on sheet 180
ROMD5: R1067.2 ; also on sheet 180
ROMD6: R1085.2 ; also on sheet 180
ROMD7: R1068.2 ; also on sheet 180
RST_PCIE_PCH_DEV_N: R656.1 ; also on sheet 51 64 83
SMB_BMC_MEZZ_SCL: BMC1.G5(GPIOK6_SCL8) R2049.1 ; also on sheet 95
SMB_BMC_MEZZ_SDA: BMC1.F3(GPIOK7_SDA8) R2042.1 ; also on sheet 95
SMB_BMC_RSVD_SCL: BMC1.C5(GPIOA4_TIMER5_SCL9) R2048.1
SMB_BMC_RSVD_SDA: BMC1.B4(GPIOA5_TIMER6_SDA9) R2041.1
SMB_HOST_STBY_LVC3_CLK: BMC1.E3(GPIOK0_SCL5) JP12.1 R2051.1 ; also on sheet 47 55 90 161
SMB_HOST_STBY_LVC3_DATA: BMC1.D2(GPIOK1_SDA5) JP12.2 R2052.1 ; also on sheet 47 55 90 161
SMB_MAIN_CLK: BMC1.E2(GPIOK4_SCL7) R2055.1 ; also on sheet 94
SMB_MAIN_DATA: BMC1.D1(GPIOK5_SDA7) R2095.1 ; also on sheet 94
SMB_PMBUS_BMC_STBY_LVC3_CLK: BMC1.J19(SCL2) JP9.1 R2037.1 ; also on sheet 60 90 162
SMB_PMBUS_BMC_STBY_LVC3_DATA: BMC1.J18(SDA2) JP9.2 R2036.1 ; also on sheet 60 90 162
SMB_SENSOR_CLK: BMC1.C1(GPIOK2_SCL6) R2046.1 ; also on sheet 52 159 184
SMB_SENSOR_DAT: BMC1.F4(GPIOK3_SDA6) R2040.1 ; also on sheet 52 159 184
SMB_SMLINK0_STBY_LVC3_CLK: BMC1.D3(GPIOQ0_SCL3) JP10.1 R2035.1 ; also on sheet 90
SMB_SMLINK0_STBY_LVC3_DATA: BMC1.C2(GPIOQ1_SDA3) JP10.2 R2034.1 ; also on sheet 90
SMB_VR_STBY_LVC3_CLK: BMC1.B1(GPIOQ2_SCL4) ; also on sheet 16 21 26 31 35 39 161
SMB_VR_STBY_LVC3_DATA: BMC1.F5(GPIOQ3_SDA4) ; also on sheet 16 21 26 31 35 39 161
VR_FAIL_PVCC_CPU_N: BMC1.E5(GPIOC3_SD1DAT1_SDA11) ; also on sheet 16 21 26 31 35 39

Not connected (* = marked no-connect by the designer): BMC1 F18(GPIOB3_SALT4)* H21(NC#H21)* H22(NC#H22)* V16(MIOZ)*; JP1 3*; U33 J1(NC#J1)* J9(NC#J9)* L1(NC#L1)* L9(NC#L9)* M7(NC#M7)*; U150 6(O)* 8(O)* 12(O)*

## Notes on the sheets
sheet 72
- AST1250 HARDWARE TRAPPING
- When no firmware existed,
  BMC must be disabled to prevent mal-function.
- ================================================================================================================
  HWTrap define the chip oeration mode before software runs.
  The HWTrap pins was defined at the flash memory interface ROMA[23:0] and ROMD[7:0].
  When SRST# reset input is low, the voltage state at these pins will be latched into an
  internal register set and keep the value unchanged after SRST# goes high.
  These HWTrap pins had embedded an internal resistor of value between 33K to 89K £[.
  To set the trap value to logic '1', pull-up the pin to 3.3V standby power by a resistor of value 1K ~ 4.7K £[ .
  To set the trap value to logic '0', just leave the pin floating.
  ================================================================================================================
- FAB2 REV001 20150702
- 1-2
- BMC disable
- 2-3(Default)
- BMC enable
- FAB1 20150226
- ROMA[1:0]  BMC CPU boot code selection
  ( )  00: Boot from NOR flash memory
  ( )  01: Boot from NAND flash memory
  (*)  10: Boot from SPI flash memory
  ( )  11: Disable ARM CPU operation
  ROMA[3:2]  VGA memory size selection
  (*)  00: Select 8 MB VGA memory
  ( )  01: Select 16 MB VGA memory
  ( )  10: Select 32 MB VGA memory
  ( )  11: Select 64 MB VGA memory
  Defined the VGA memory size that will share with SOC
  memory.
  ROMA[4]  Boot flash memory extended option
  NOR type flash: data bus width selection
  ( )  0: Select 8 bits interface
  ( )  1: Select 16 bits interface
  SPI type flash: boot address mode selection
  (*)  0: Boot with 24 bits address mode
  ( )  1: Boot with 32 bits address mode
  This setting apply to both 1st and 2nd boot flash CS0#
  and CS1#.
  ROMA[5]  Enable VGA BIOS ROM
  (*)  0: No VGA BISO ROM (for on-board applications)
  ( )  1: Enable VGA BIOS ROM (for add-on card
  applications)
  ROMA[6]  Define MAC#1 interface
  (*)  0: RMII/NCSI
  ( )  1: RGMII
  ROMA[7]  Define MAC#2 interface
  (*)  0: RMII/NCSI
  ( )  1: RGMII
  ROMA[9:8]  H-PLL default clock frequency selection
  (*)  00: Select 384 MHz
  ( )  01: Select 360 MHz
  ( )  10: Select 336 MHz
  ( )  11: Select 408 MHz
  ROMA[11:10]  CPU/AHB clock frequency ratio selection
  ( )  00: Select CPU:AHB = 1:1
  (*)  01: Select CPU:AHB = 2:1
  ( )  10: Select CPU:AHB = 4:1
  ( )  11: Select CPU:AHB = 3:1
  ROMA[13:12]  SPI mode selection
  ( )  00: Disable SPI interface
  (*)  01: Enable SPI Master
  ( )  10: Enable SPI Master and SPI Slave to AHB Bridge
  ( )  11: Enable SPI Bypass
- EVT 20150126
- ROMA[14]  Enable LPC dedicated reset pin function
  ( )  0: LPC reset is shared with PCI reset pin
  (*)  1: LPC reset is located at pin number E19, shared with GPIOB4.
  ROMA[15]  VGA Class Code selection
  ( )  0: Select the Class Code for video device
  (*)  1: Select the Class Code for VGA device
  ROMA[16]  SuperIO configuration address selection
  (*)  0: Decode 0x2E
  ( )  1: Decode 0x4E
  ROMA[17]  Enable BMC 2nd boot watchdog timer
  (*)  0: Disable
  ( )  1: Enable BMC 2nd boot watchdog timer start counting at power up.
  The watchdog timer was located at WDT2. After watchdog timeout, it
  will reset BMC and restart booting from the 2nd boot flash at CS1#.
  CS1# must be the same flash type as CS0# and could be the same
  firmware as CS0#.
  ROMA[23, 18]  Clock source selection
  ( )  00: 24 MHz
  (*)  01: 48 MHz
  ( )  10:  CLKIN=25 MHz, USBCKI=24 MHz
  ( )  11:  CLKIN=25 MHz, USBCKI=48 MHz
  ROMA[19]  Disable ACPI function
  ( )  0: Enable ACPI
  (*)  1: Disable ACPI
  ROMA[20]  Disable LPC to decode SuperIO 0x2E/0x4E address
  (*)  0: Enable address decoding
  ( )  1: Disable address decoding
  ROMA[21]  Enable GPIOD pass-through mode
  (* )  0: Disable, pass through can be enabled by SCU8C[11:8].
  ()  1: Enable pass-through at power on.
  Pass-through pins set:
  GPIOD0 △ GPIOD1
  GPIOD2 △ GPIOD3
  GPIOD4 △ GPIOD5
  GPIOD6 △ GPIOD7
  ROMA[22]  Enable GPIOE pass-through mode
  (*)  0: Disable, pass through can be enabled by SCU8C[15:12].
  ( )  1: Enable pass-through at power on.
  Pass-through pins set:
  GPIOE0 △ GPIOE1
  GPIOE2 △ GPIOE3
  GPIOE4 △ GPIOE5
  GPIOE6 △ GPIOE7
- ROMD[2:0]  DRAM configuration setting
  ( )  000: DDR3 SDRAM with CL = 5, CWL = 5
  (*)  010: DDR3 SDRAM with CL = 6, CWL = 5
  ( )  100: DDR3 SDRAM with CL = 7, CWL = 6
  ( )  110: DDR3 SDRAM with CL = 8, CWL = 6
  ( )  001: DDR2 SDRAM with CL = 4
  ( )  011: DDR2 SDRAM with CL = 5
  ( )  101: DDR2 SDRAM with CL = 6
  ( )  111: DDR2 SDRAM with CL = 7
  The DRAM configuration setting is defined for compliant VGA
  BIOS/Driver and BMC firmware default supported DRAM timing.
  When using different types of DRAM, it must modify the trap-
  ping setting to get correct DRAM timing initialization.
  When the used DRAM speed bin not meet the supported value.
  It must to change the firmware and also the VBIOS to
  dedicate support this DRAM. And AST2300 VGA must be the
  primary display adapter.
  ROMD[4:3]  DRAM size setting (for VGA driver use)
  (*)  00:  64 MBytes
  ( )  01: 128 MBytes
  ( )  10: 256 MBytes
  ( )  11: 512 MBytes
  The size setting is defined for VGA driver use only.
  BMC firmware and VGA BIOS don't read this setting but must
  set this field to correct value. For BMC firmware and VGA
  BIOS, the size information is fixed in code.
  For VGA only application (no BMC), such as AST1300, the
  external hardware trapping must set correctly.
  ROMD[7:5]  Software defined trapping registers
  These bits are reserved for future design.
  System and Software designer can use these bits to define
  some board or firmware option mode.
sheet 73
- AST1250 POWER
- EVT 20150126
- 0603
- H21,H22 should tie
  to GND or NC when no
  use.
- MVD1
- MVD2
- Place under BGA at least
  5 power vias.
- Near Pin F10, F11
- Near Pin F8, F9
- PVD1
- PVD2
- PVD3
sheet 74
- AST1250 PCIE_LPC_DDR3_I2C
- 0.1U 16V K0402 X7R
- PCI-E/VGA can be
  disabled by
  pulling PERST#
  low, and KVM
  function will not
  work when VGA is
  disabled.
- Layout Note:
  Place CAPs close to power pins.
- DDRIII
- 1Gb: 64Meg x16
- Differential Pair
- FAB2 REV001 20150610
- Pull-up selection must meet:
  rising time < 1 us
- FAB2 REV001 20150610
- Differential Pair
- Layout Note:
  Place CAP close
  to pin.
- FAB1 REV004 20150320
- FAB1 REV002 20150317
- I2C/SMBus
- FAB1 REV004 20150320
- FAB1 20150211
- FAB1 20150206
- DDR3 Vref
- FAB2 REV001 20150630
- Trace width >= 15 mils
- FAB1 REV013 20150413
- Change to 75.04001.07C
sheet 75
- Capacitors
- FAB1 REV005 20150323
sheet 76
- AST1250 HEARTBEAT_ADC
- BMC Heartbeat LED
- ADC Voltage Divider
- ADC input voltage range: 0~2.5V
  A good nominal input voltage = 3/4 VI_max = 1.8V
- Please place close to BMC0.
- CATERR LED
- Please place close to BMC0.
- FAB2 REV001 20150616
- HEX INVERTER BUFFERS/DRIVERS
  WITH OPEN-DRAIN OUTPUTS
- Isolated Circuit
- to BMC
- FAB3 REV001 20151014
- to BMC
sheet 77
- SMBUS HEADER
- FAB1 20150127
- FAB1 REV026 20150506
- Remove JP11
